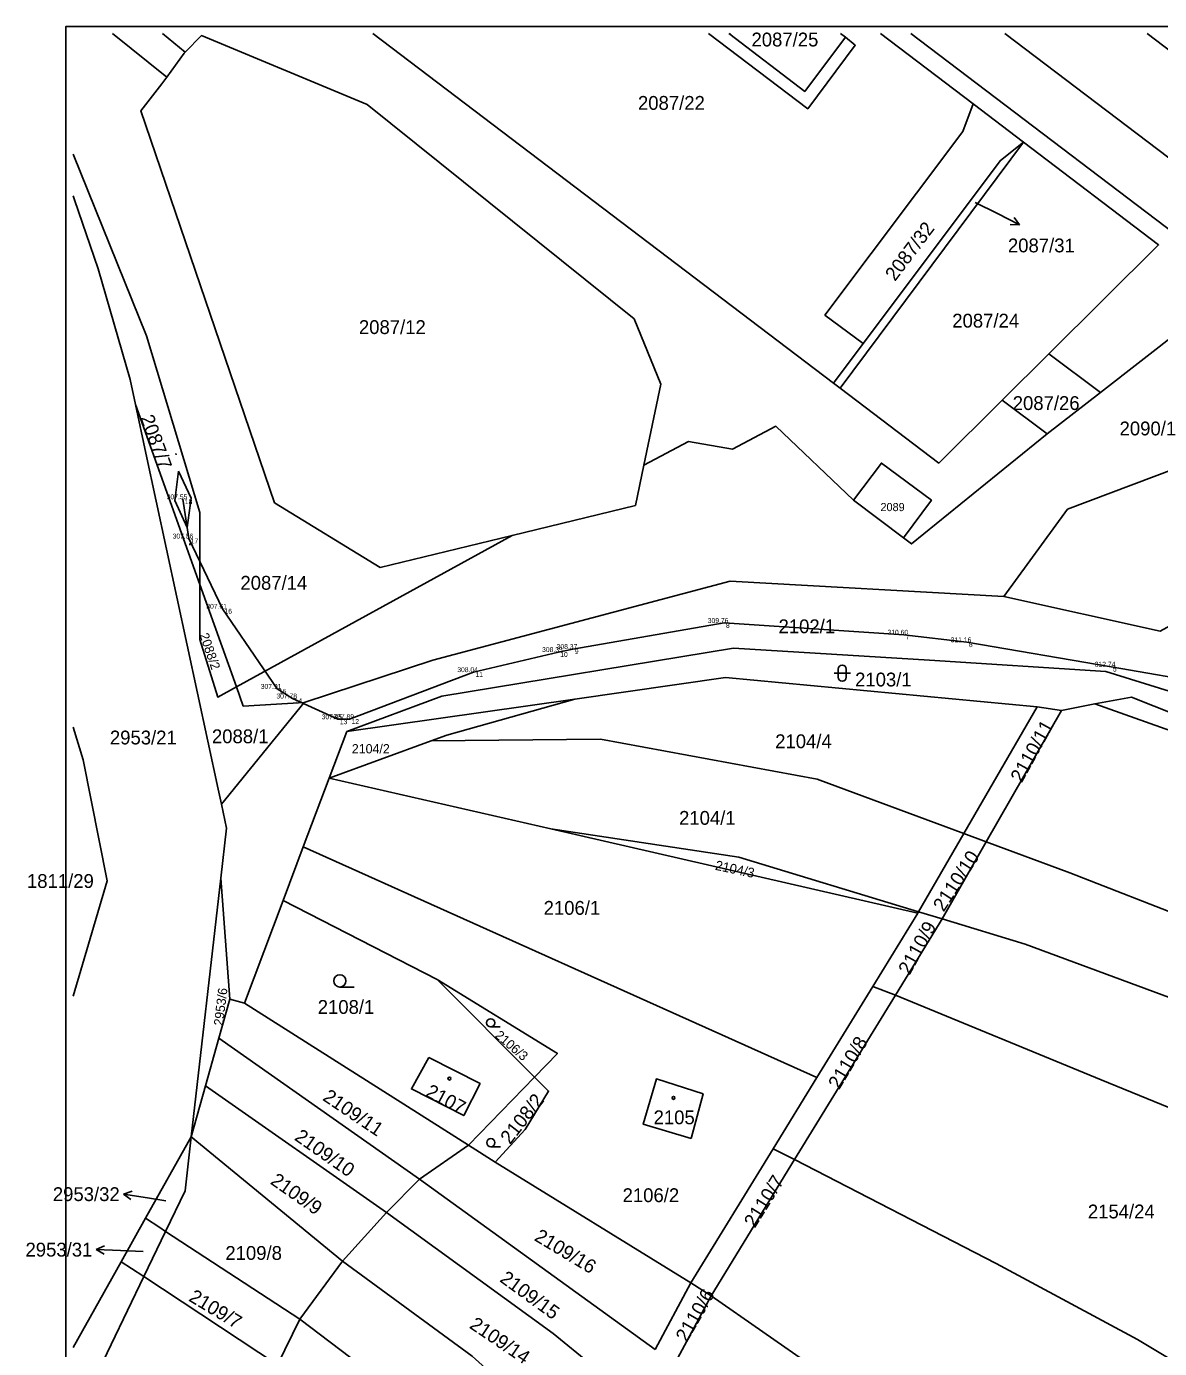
# Model space of a CAD drawing. Extents: x -606208 to -605570, y -1157873 to -1157573.
# Drawn here: x -606208.1 to -606068.9, y -1157739 to -1157576.5 of the extents above; entities that cross this region are included whole.
import ezdxf

# ---------------------------------------------------------------- set-up
doc = ezdxf.new("R2010")
doc.units = 0
for name, color, linetype in [('Vrstva 1', 7, 'Continuous'), ('Vrstva 23', 7, 'Continuous'), ('Vrstva 30', 7, 'Continuous'), ('Vrstva 58', 7, 'Continuous'), ('Vrstva 59', 7, 'Continuous'), ('Vrstva 60', 7, 'Continuous'), ('Vrstva 62', 7, 'Continuous')]:
    doc.layers.add(name, color=color, linetype=linetype)

msp = doc.modelspace()

# ---------------------------------------------------------------- linework, layer by layer
at = {"layer": 'Vrstva 1'}
msp.add_lwpolyline([(-606203.28, -1157873.46), (-605573.29, -1157873.46), (-605573.29, -1157576.47), (-606203.28, -1157576.47)], close=True, dxfattribs=at)
at = {"layer": 'Vrstva 23'}
for p, q in [((-606189.73, -1157629.15), (-606189.76, -1157628.95)), ((-606188.07, -1157640.03), (-606188.04, -1157640.23))]:
    msp.add_line(p, q, dxfattribs=at)
msp.add_lwpolyline([(-606189.43, -1157631.13), (-606189.89, -1157634.74), (-606188.37, -1157638.05), (-606187.91, -1157634.44)], close=True, dxfattribs=at)
at = {"layer": 'Vrstva 30'}
msp.add_lwpolyline([(-606188.9, -1157634.59), (-606188.17, -1157639.42), (-606184.03, -1157648.05), (-606177.34, -1157657.9), (-606175.42, -1157659.08), (-606169.85, -1157661.64), (-606168.42, -1157661.61), (-606153.19, -1157655.84), (-606142.77, -1157653.37), (-606140.98, -1157653), (-606122.41, -1157649.8), (-606100.33, -1157651.24), (-606092.56, -1157652.17), (-606074.86, -1157655.17), (-606062.53, -1157657.3)], dxfattribs=at)
at = {"layer": 'Vrstva 60'}
for p, q in [((-606188.9, -1157634.59), (-606188.9, -1157634.59)), ((-606188.17, -1157639.42), (-606188.17, -1157639.42)), ((-606184.03, -1157648.05), (-606184.03, -1157648.05)), ((-606122.41, -1157649.8), (-606122.41, -1157649.8)), ((-606100.33, -1157651.24), (-606100.33, -1157651.24)), ((-606092.56, -1157652.17), (-606092.56, -1157652.17)), ((-606142.77, -1157653.37), (-606142.77, -1157653.37)), ((-606140.98, -1157653), (-606140.98, -1157653)), ((-606153.19, -1157655.84), (-606153.19, -1157655.84)), ((-606074.86, -1157655.17), (-606074.86, -1157655.17)), ((-606177.34, -1157657.9), (-606177.34, -1157657.9)), ((-606175.42, -1157659.08), (-606175.42, -1157659.08)), ((-606169.85, -1157661.64), (-606169.85, -1157661.64)), ((-606168.42, -1157661.61), (-606168.42, -1157661.61))]:
    msp.add_line(p, q, dxfattribs=at)
at = {"layer": 'Vrstva 62'}
for p, q in [((-606121.69, -1157577.43), (-606121.81, -1157577.34)), ((-606108.1, -1157577.34), (-606107.5, -1157577.8)), ((-606091.81, -1157586), (-606085.61, -1157590.71)), ((-606085.61, -1157590.71), (-606108.16, -1157620.92)), ((-606091.56, -1157598.1), (-606088.79, -1157599.48)), ((-606088.79, -1157599.48), (-606086.12, -1157600.84)), ((-606086.12, -1157600.84), (-606086.78, -1157599.94)), ((-606086.12, -1157600.84), (-606087.24, -1157600.83)), ((-606108.97, -1157620.31), (-606105.33, -1157615.44)), ((-606082.52, -1157616.73), (-606088.24, -1157622.41)), ((-606082.52, -1157616.73), (-606076.16, -1157621.45)), ((-606108.16, -1157620.92), (-606108.97, -1157620.31)), ((-606076.16, -1157621.45), (-606082.71, -1157626.53)), ((-606194.73, -1157622.94), (-606186.82, -1157645.08)), ((-606082.71, -1157626.53), (-606088.24, -1157622.41)), ((-606106.52, -1157634.71), (-606100.37, -1157639.33)), ((-606148.43, -1157639.03), (-606182.33, -1157657.65)), ((-606182.33, -1157657.65), (-606186.82, -1157645.08)), ((-606108.39, -1157655.47), (-606108.39, -1157656.47)), ((-606107.39, -1157656.47), (-606107.39, -1157655.47)), ((-606108.89, -1157655.97), (-606106.89, -1157655.97)), ((-606168.75, -1157663.12), (-606140.76, -1157659.15)), ((-606184.18, -1157672.06), (-606173.99, -1157659.59)), ((-606092.96, -1157675.69), (-606083.95, -1157660.1)), ((-606090.2, -1157676.71), (-606080.96, -1157660.54)), ((-606083.95, -1157660.1), (-606080.96, -1157660.54)), ((-606080.96, -1157660.54), (-606076.85, -1157659.75)), ((-606170.95, -1157668.86), (-606168.75, -1157663.12)), ((-606170.95, -1157668.86), (-606158.4, -1157664.3)), ((-606174.13, -1157677.33), (-606170.95, -1157668.86)), ((-606143.7, -1157675.12), (-606170.95, -1157668.86)), ((-606098.62, -1157685.47), (-606143.7, -1157675.12)), ((-606098.51, -1157685.29), (-606092.96, -1157675.69)), ((-606095.61, -1157686.17), (-606090.2, -1157676.71)), ((-606090.2, -1157676.71), (-606092.96, -1157675.69)), ((-606079.93, -1157680.52), (-606090.2, -1157676.71)), ((-606176.6, -1157683.9), (-606174.13, -1157677.33)), ((-606174.13, -1157677.33), (-606111, -1157705.66)), ((-606184.24, -1157681.18), (-606187.88, -1157712.95)), ((-606184.24, -1157681.18), (-606183.13, -1157696.05)), ((-606026.37, -1157701.43), (-606079.93, -1157680.52)), ((-606181.35, -1157696.53), (-606176.6, -1157683.9)), ((-606176.6, -1157683.9), (-606157.67, -1157693.62)), ((-606104.14, -1157694.47), (-606098.62, -1157685.47)), ((-606098.62, -1157685.47), (-606098.51, -1157685.29)), ((-606095.61, -1157686.17), (-606098.51, -1157685.29)), ((-606169.62, -1157694.55), (-606167.87, -1157694.55)), ((-606157.67, -1157693.62), (-606145.7, -1157705.61)), ((-606111, -1157705.66), (-606104.14, -1157694.47)), ((-606101.34, -1157695.55), (-606104.14, -1157694.47)), ((-606184.48, -1157700.84), (-606183.13, -1157696.05)), ((-606183.13, -1157696.05), (-606181.35, -1157696.53)), ((-606181.35, -1157696.53), (-606153.8, -1157714)), ((-606113.74, -1157715.77), (-606101.34, -1157695.55)), ((-606151.08, -1157699.45), (-606149.91, -1157699.45)), ((-606186.13, -1157706.71), (-606184.48, -1157700.84)), ((-606159.85, -1157718.17), (-606184.48, -1157700.84)), ((-606153.8, -1157714), (-606145.7, -1157705.61)), ((-606116.38, -1157714.43), (-606111, -1157705.66)), ((-606187.88, -1157712.95), (-606186.13, -1157706.71)), ((-606163.89, -1157722.28), (-606186.13, -1157706.71)), ((-606193.49, -1157722.97), (-606187.88, -1157712.95)), ((-606169.28, -1157728.25), (-606187.88, -1157712.95)), ((-606159.85, -1157718.17), (-606153.8, -1157714)), ((-606153.8, -1157714), (-606150.52, -1157716.08)), ((-606151.07, -1157714.18), (-606149.89, -1157714.18)), ((-606126.5, -1157730.93), (-606116.38, -1157714.43)), ((-606113.74, -1157715.77), (-606116.38, -1157714.43)), ((-606150.52, -1157716.08), (-606126.5, -1157730.93)), ((-606123.99, -1157732.49), (-606113.74, -1157715.77)), ((-606163.89, -1157722.28), (-606159.85, -1157718.17)), ((-606130.89, -1157739.11), (-606159.85, -1157718.17)), ((-606196.21, -1157720), (-606195.15, -1157719.66)), ((-606193.25, -1157720.47), (-606196.21, -1157720)), ((-606196.21, -1157720), (-606195.3, -1157720.65)), ((-606191.02, -1157720.82), (-606193.25, -1157720.47)), ((-606169.28, -1157728.25), (-606163.89, -1157722.28)), ((-606196.49, -1157728.31), (-606193.49, -1157722.97)), ((-606193.72, -1157730.15), (-606191.04, -1157724.59)), ((-606174.52, -1157735.38), (-606191.04, -1157724.59)), ((-606199.57, -1157726.83), (-606198.55, -1157726.37)), ((-606196.57, -1157726.94), (-606199.57, -1157726.83)), ((-606199.57, -1157726.83), (-606198.59, -1157727.37)), ((-606193.77, -1157727.04), (-606196.57, -1157726.94)), ((-606174.52, -1157735.38), (-606169.28, -1157728.25)), ((-606202.41, -1157748.21), (-606193.72, -1157730.15)), ((-606177.29, -1157741.01), (-606193.72, -1157730.15)), ((-606130.89, -1157739.11), (-606126.5, -1157730.93)), ((-606123.99, -1157732.49), (-606126.5, -1157730.93)), ((-606128.47, -1157740.84), (-606123.99, -1157732.49)), ((-606177.29, -1157741.01), (-606174.52, -1157735.38))]:
    msp.add_line(p, q, dxfattribs=at)
for points in [[(-606197.54, -1157577.34), (-606190.9, -1157582.7)], [(-606191.42, -1157577.34), (-606188.61, -1157579.62)], [(-606188.61, -1157579.62), (-606186.63, -1157577.6), (-606166.27, -1157586.06), (-606133.46, -1157612.43), (-606130.17, -1157620.45), (-606132.25, -1157630.42)], [(-606108.97, -1157620.31), (-606165.55, -1157577.34)], [(-606107.5, -1157577.8), (-606106.28, -1157578.79), (-606112.12, -1157586.58), (-606124.32, -1157577.34)], [(-606121.63, -1157577.34), (-606121.69, -1157577.43), (-606112.5, -1157584.46), (-606107.5, -1157577.8)], [(-606103.2, -1157577.34), (-606091.81, -1157586)], [(-606058.87, -1157608.16), (-606099.48, -1157577.34)], [(-606052.84, -1157603.93), (-606087.9, -1157577.34)], [(-606043.78, -1157597.57), (-606067.34, -1157579.69), (-606070.43, -1157577.34)], [(-606188.61, -1157579.62), (-606188.76, -1157579.76), (-606190.9, -1157582.7)], [(-606190.9, -1157582.7), (-606191.51, -1157583.51), (-606194.09, -1157586.84), (-606177.66, -1157635.02), (-606164.66, -1157642.97), (-606148.43, -1157639.03)], [(-606105.33, -1157615.44), (-606110.02, -1157611.95), (-606093.09, -1157589.38), (-606091.81, -1157586)], [(-606085.61, -1157590.71), (-606088.46, -1157592.93), (-606105.33, -1157615.44)], [(-606085.61, -1157590.71), (-606069.02, -1157603.32), (-606082.52, -1157616.73)], [(-606186.82, -1157645.08), (-606186.82, -1157636.2), (-606193.39, -1157614.51), (-606202.41, -1157592.17)], [(-606202.41, -1157597.28), (-606202.23, -1157597.78), (-606199.34, -1157606.25), (-606195.38, -1157619.87), (-606194.73, -1157622.94)], [(-606076.16, -1157621.45), (-606061.16, -1157609.77), (-606058.87, -1157608.16)], [(-606088.05, -1157646.56), (-606080.19, -1157635.82), (-606064.22, -1157629.8), (-606051.47, -1157621.02), (-606048, -1157616.41)], [(-606088.24, -1157622.41), (-606096.02, -1157630.14), (-606108.16, -1157620.92)], [(-606194.73, -1157622.94), (-606193.45, -1157628.93), (-606184.58, -1157670.21), (-606184.18, -1157672.06)], [(-606132.25, -1157630.42), (-606126.76, -1157627.5), (-606121.37, -1157628.44), (-606116.04, -1157625.61), (-606106.52, -1157634.71)], [(-606100.37, -1157639.33), (-606099.38, -1157640.07), (-606082.71, -1157626.53)], [(-606132.25, -1157630.42), (-606133.31, -1157635.35), (-606148.43, -1157639.03)], [(-606106.52, -1157634.71), (-606103.07, -1157630.15), (-606096.93, -1157634.72), (-606100.37, -1157639.33)], [(-606182.33, -1157657.65), (-606184.63, -1157658.9), (-606186.82, -1157651.83), (-606186.82, -1157645.08)], [(-606088.05, -1157646.56), (-606121.64, -1157644.65), (-606158.19, -1157654.38), (-606173.99, -1157659.59)], [(-606058.47, -1157651.46), (-606064.55, -1157648.46), (-606068.82, -1157650.81), (-606088.05, -1157646.56)], [(-606168.75, -1157663.12), (-606157.1, -1157658.79), (-606121.27, -1157652.9), (-606097.17, -1157654.39), (-606075.51, -1157655.76), (-606047.27, -1157664.52), (-606027.99, -1157676.53)], [(-606140.76, -1157659.15), (-606122.22, -1157656.52), (-606083.95, -1157660.1)], [(-606173.99, -1157659.59), (-606181.49, -1157660.01), (-606182.33, -1157657.65)], [(-606158.4, -1157664.3), (-606156.47, -1157663.6), (-606140.76, -1157659.15)], [(-606076.85, -1157659.75), (-606072.33, -1157658.9), (-606027.99, -1157676.53)], [(-606076.85, -1157659.75), (-606050.81, -1157669), (-606049.26, -1157669.9), (-606025.74, -1157683.6)], [(-606202.41, -1157695.66), (-606198.23, -1157681.48), (-606201.18, -1157666.64), (-606202.41, -1157662.59)], [(-606092.96, -1157675.69), (-606110.99, -1157669), (-606137.6, -1157664.08), (-606158.4, -1157664.3)], [(-606184.18, -1157672.06), (-606183.54, -1157675.03), (-606184.24, -1157681.18)], [(-606143.7, -1157675.12), (-606120.58, -1157678.59), (-606098.51, -1157685.29)], [(-606101.34, -1157695.55), (-606095.97, -1157686.79), (-606095.61, -1157686.17)], [(-606038.6, -1157709.02), (-606053.11, -1157701.37), (-606057.71, -1157699.53), (-606085.4, -1157689.27), (-606095.61, -1157686.17)], [(-606157.67, -1157693.62), (-606142.89, -1157702.7), (-606145.7, -1157705.61)], [(-606031.93, -1157728.32), (-606058.33, -1157713.22), (-606076.06, -1157705.96), (-606101.34, -1157695.55)], [(-606158.68, -1157703.22), (-606160.83, -1157707.07), (-606154.39, -1157710.36), (-606152.38, -1157706.42), (-606158.68, -1157703.22)], [(-606145.7, -1157705.61), (-606143.98, -1157707.33), (-606146.85, -1157712.05), (-606150.52, -1157716.08)], [(-606126.46, -1157713.15), (-606124.99, -1157707.67), (-606130.72, -1157705.85), (-606132.35, -1157711.41), (-606126.46, -1157713.15)], [(-606191.04, -1157724.59), (-606188.64, -1157719.6), (-606187.88, -1157712.95)], [(-606056.89, -1157746.69), (-606071.62, -1157737.87), (-606088.96, -1157728.54), (-606113.74, -1157715.77)], [(-606133.98, -1157744.86), (-606143.4, -1157737.14), (-606163.89, -1157722.28)], [(-606191.04, -1157724.59), (-606191.76, -1157724.11), (-606193.49, -1157722.97)], [(-606202.41, -1157738.87), (-606196.49, -1157728.31)], [(-606193.72, -1157730.15), (-606195.21, -1157729.16), (-606196.49, -1157728.31)], [(-606138.5, -1157753.29), (-606153.37, -1157739.93), (-606169.28, -1157728.25)], [(-606123.99, -1157732.49), (-606092.27, -1157754.64), (-606071.11, -1157770.44)], [(-606142.97, -1157761.61), (-606160.8, -1157745.8), (-606174.52, -1157735.38)]]:
    msp.add_lwpolyline(points, dxfattribs=at)
for centre, radius in [((-606169.62, -1157693.8), 0.75), ((-606151.09, -1157698.95), 0.502), ((-606156.16, -1157705.81), 0.175), ((-606128.62, -1157708.18), 0.175), ((-606151.07, -1157713.68), 0.502)]:
    msp.add_circle(centre, radius, dxfattribs=at)
for centre, start, end in [((-606107.89, -1157655.47), 0, 180), ((-606107.89, -1157656.47), 180, 359.9879)]:
    msp.add_arc(centre, 0.5, start, end, dxfattribs=at)

# ---------------------------------------------------------------- texts
at = {"layer": 'Vrstva 58'}
for s, p in [('307.55 ', (-606190.9, -1157634.59)), ('307.56 ', (-606190.17, -1157639.42)), ('307.61 ', (-606186.03, -1157648.05)), ('309.76 ', (-606124.41, -1157649.8)), ('310.60 ', (-606102.33, -1157651.24)), ('308.37 ', (-606142.98, -1157653)), ('311.16 ', (-606094.56, -1157652.17)), ('308.35 ', (-606144.77, -1157653.37)), ('308.04 ', (-606155.19, -1157655.84)), ('312.74 ', (-606076.86, -1157655.17)), ('307.91 ', (-606179.34, -1157657.9)), ('307.78 ', (-606177.42, -1157659.08)), ('307.95 ', (-606171.85, -1157661.64)), ('307.89 ', (-606170.42, -1157661.61))]:
    msp.add_text(s, height=0.6, dxfattribs=at).set_placement(p)
at = {"layer": 'Vrstva 59'}
for s, p in [(' 18', (-606188.9, -1157635.19)), (' 17', (-606188.17, -1157640.02)), (' 16', (-606184.03, -1157648.65)), (' 8', (-606122.41, -1157650.4)), (' 7', (-606100.33, -1157651.84)), (' 6', (-606092.56, -1157652.77)), (' 10', (-606142.77, -1157653.97)), (' 9', (-606140.98, -1157653.6)), (' 11', (-606153.19, -1157656.44)), (' 5', (-606074.86, -1157655.77)), (' 15', (-606177.34, -1157658.5)), (' 14', (-606175.42, -1157659.68)), (' 13', (-606169.85, -1157662.24)), (' 12', (-606168.42, -1157662.21))]:
    msp.add_text(s, height=0.6, dxfattribs=at).set_placement(p)
at = {"layer": 'Vrstva 62'}
for s, height, p in [('2087/25', 1.7, (-606119.04, -1157578.93)), ('2087/22', 1.7, (-606132.99, -1157586.72)), ('2087/31', 1.7, (-606087.53, -1157604.24)), ('2087/24', 1.7, (-606094.37, -1157613.49)), ('2087/12', 1.7, (-606167.28, -1157614.28)), ('2087/26', 1.7, (-606086.94, -1157623.62)), ('2090/1', 1.7, (-606073.81, -1157626.74)), ('2089', 1, (-606103.19, -1157636.05)), ('2087/14', 1.7, (-606181.84, -1157645.71)), ('2102/1', 1.7, (-606115.72, -1157651.06)), ('2103/1', 1.7, (-606106.31, -1157657.6)), ('2953/21', 1.7, (-606197.88, -1157664.73)), ('2088/1', 1.7, (-606185.34, -1157664.58)), ('2104/4', 1.7, (-606116.13, -1157665.19)), ('2104/2', 1.14, (-606168.15, -1157665.83)), ('2104/1', 1.7, (-606127.94, -1157674.61)), ('1811/29', 1.7, (-606208.07, -1157682.37)), ('2106/1', 1.7, (-606144.58, -1157685.67)), ('2108/1', 1.7, (-606172.34, -1157697.85)), ('2105', 1.7, (-606131.07, -1157711.42)), ('2953/32', 1.7, (-606204.89, -1157720.86)), ('2106/2', 1.7, (-606134.88, -1157720.99)), ('2154/24', 1.7, (-606077.71, -1157722.99)), ('2953/31', 1.7, (-606208.25, -1157727.68)), ('2109/8', 1.7, (-606183.69, -1157728.09))]:
    msp.add_text(s, height=height, dxfattribs=at).set_placement(p)
for s, height, rotation, p in [('2087/32', 1.7, 53, (-606101.4, -1157607.88)), ('2087/7', 1.7, 290, (-606194.17, -1157624.55)), ('2088/2', 1.14, 289, (-606186.88, -1157651.25)), ('2110/11', 1.7, 61, (-606085.84, -1157669.55)), ('2110/10', 1.7, 57, (-606095.43, -1157685.4)), ('2104/3', 1.19, 348, (-606123.57, -1157680.13)), ('2110/9', 1.7, 61, (-606099.62, -1157693.18)), ('2953/6', 1.14, 83, (-606183.99, -1157699.36)), ('2106/3', 1.14, 319, (-606150.64, -1157700.64)), ('2110/8', 1.7, 59, (-606108.27, -1157707.25)), ('2109/11', 1.7, 326, (-606171.84, -1157708.39)), ('2107', 1.7, 332, (-606159.21, -1157707.9)), ('2108/2', 1.7, 52, (-606148.71, -1157713.99)), ('2109/10', 1.7, 325, (-606175.31, -1157713.27)), ('2109/9', 1.7, 325, (-606178.27, -1157718.67)), ('2110/7', 1.7, 58, (-606118.64, -1157724.27)), ('2109/16', 1.7, 329, (-606145.84, -1157725.63)), ('2109/15', 1.7, 324, (-606150.08, -1157730.68)), ('2109/7', 1.7, 329, (-606188.3, -1157733.06)), ('2110/6', 1.7, 60, (-606126.99, -1157738.32)), ('2109/14', 1.7, 326, (-606153.81, -1157736.39))]:
    msp.add_text(s, height=height, rotation=rotation, dxfattribs=at).set_placement(p)

doc.saveas('drawing.dxf')
